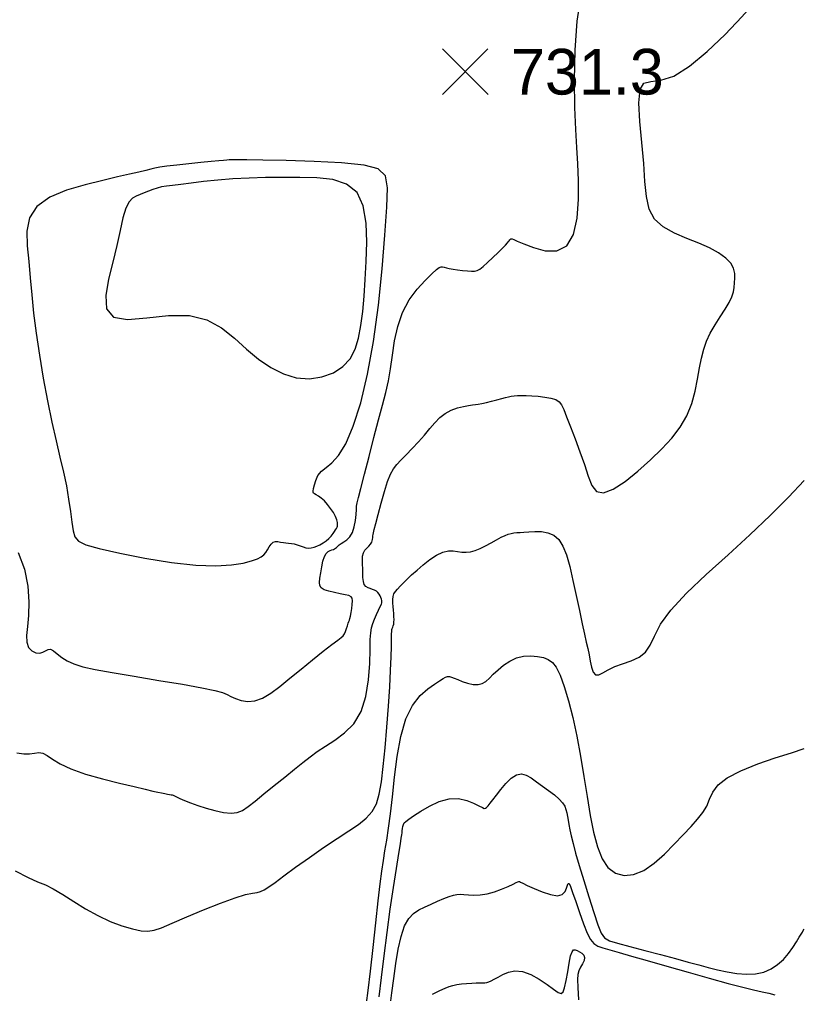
# Model space of a CAD drawing. Extents: x 2566142 to 2571431, y 418755 to 421584.
# Drawn here: x 2567510.9 to 2567768.3, y 419780.6 to 420100.3 of the extents above; entities that cross this region are included whole.
import ezdxf

# ---------------------------------------------------------------- set-up
doc = ezdxf.new("R2010")
doc.units = 0
for name, color, linetype in [('Contour_ADS_Major', 7, 'Continuous'), ('Contour_ADS_Minor', 7, 'Continuous'), ('Contour_ADS_Spot_Elevation', 7, 'Continuous')]:
    doc.layers.add(name, color=color, linetype=linetype)

# ---------------------------------------------------------------- blocks, each defined once
blk = doc.blocks.new('S750')
at = {"layer": 'Contour_ADS_Spot_Elevation'}
for p, q in [((-0.5, 0.498), (0.5, -0.498)), ((-0.498, -0.5), (0.498, 0.5))]:
    blk.add_line(p, q, dxfattribs=at)

msp = doc.modelspace()

# ---------------------------------------------------------------- linework, layer by layer
at = {"layer": 'Contour_ADS_Major'}
for points in [[(2567617.86, 419911.52), (2567616.2, 419911.84), (2567614.29, 419912.21), (2567612.43, 419912.64), (2567610.9, 419913.15), (2567609.95, 419913.75), (2567609.5, 419914.52), (2567609.41, 419915.55), (2567609.54, 419916.93), (2567609.78, 419918.69), (2567610.1, 419920.63), (2567610.5, 419922.5), (2567611, 419924.04), (2567611.58, 419925.07), (2567612.22, 419925.67), (2567612.85, 419925.99), (2567613.43, 419926.18), (2567613.93, 419926.36), (2567614.34, 419926.56), (2567614.67, 419926.77), (2567614.95, 419927), (2567615.2, 419927.25), (2567615.48, 419927.54), (2567615.88, 419927.88), (2567616.49, 419928.3), (2567617.35, 419928.82), (2567618.36, 419929.54), (2567619.37, 419930.55), (2567620.22, 419931.96), (2567620.82, 419933.8), (2567621.19, 419935.85), (2567621.39, 419937.82), (2567621.49, 419939.43), (2567621.57, 419940.54), (2567621.74, 419941.63), (2567622.14, 419943.36), (2567622.91, 419946.35), (2567624.12, 419951.03), (2567625.64, 419956.85), (2567627.27, 419963.05), (2567628.81, 419968.87), (2567630.12, 419973.73), (2567631.19, 419977.87), (2567632.06, 419981.71), (2567632.75, 419985.68), (2567633.35, 419990.09), (2567634.05, 419994.81), (2567635.06, 419999.57), (2567636.63, 420004.12), (2567638.88, 420008.22), (2567641.5, 420011.77), (2567644.11, 420014.66), (2567646.31, 420016.81), (2567647.8, 420018.17), (2567648.71, 420018.89), (2567649.28, 420019.15), (2567649.75, 420019.14), (2567650.31, 420019.01), (2567651.05, 420018.82), (2567652.01, 420018.59), (2567653.24, 420018.35), (2567654.74, 420018.13), (2567656.38, 420017.93), (2567657.96, 420017.79), (2567659.31, 420017.7), (2567660.32, 420017.7), (2567661.14, 420017.89), (2567661.99, 420018.36), (2567663.09, 420019.24), (2567664.59, 420020.56), (2567666.31, 420022.15), (2567668.03, 420023.77), (2567669.48, 420025.19), (2567670.49, 420026.22), (2567671.11, 420026.92), (2567671.47, 420027.37), (2567671.69, 420027.68), (2567671.87, 420027.92), (2567672.04, 420028.12), (2567672.21, 420028.25), (2567672.38, 420028.31), (2567672.61, 420028.27), (2567673.16, 420028.05), (2567674.34, 420027.54), (2567676.45, 420026.65), (2567679.65, 420025.4), (2567683.48, 420024.38), (2567687.32, 420024.32), (2567690.57, 420025.95), (2567692.74, 420029.73), (2567693.94, 420035.11), (2567694.43, 420041.27), (2567694.45, 420047.38), (2567694.23, 420052.88), (2567693.89, 420058.23), (2567693.52, 420064.17), (2567693.24, 420071.42), (2567693.13, 420080.37), (2567693.34, 420090.18), (2567693.99, 420099.68), (2567695.24, 420107.69)], [(2567510.41, 419925.41), (2567512.52, 419919.92), (2567513.63, 419914.33), (2567513.99, 419909.12), (2567513.84, 419904.69), (2567513.47, 419901.07), (2567513.17, 419898.17), (2567513.24, 419895.91), (2567513.89, 419894.21), (2567514.97, 419893.06), (2567516.26, 419892.43), (2567517.51, 419892.31), (2567518.55, 419892.62), (2567519.42, 419893.13), (2567520.24, 419893.55), (2567521.09, 419893.6), (2567522.09, 419893.08), (2567523.28, 419892.12), (2567524.73, 419890.94), (2567526.5, 419889.77), (2567528.7, 419888.78), (2567531.65, 419887.89), (2567535.73, 419886.99), (2567541.32, 419885.97), (2567548.56, 419884.74), (2567556.6, 419883.41), (2567564.36, 419882.1), (2567570.76, 419880.96), (2567575.02, 419880.09), (2567577.55, 419879.4), (2567579.06, 419878.8), (2567580.29, 419878.15), (2567581.81, 419877.42), (2567583.68, 419876.76), (2567585.82, 419876.43), (2567588.16, 419876.65), (2567590.66, 419877.6), (2567593.35, 419879.23), (2567596.32, 419881.43), (2567599.66, 419884.11), (2567603.36, 419887.11), (2567607.13, 419890.16), (2567610.61, 419892.95), (2567613.45, 419895.18), (2567615.37, 419896.62), (2567616.53, 419897.48), (2567617.18, 419898.05), (2567617.59, 419898.63), (2567617.94, 419899.43), (2567618.28, 419900.38), (2567618.59, 419901.34), (2567618.85, 419902.16), (2567619.04, 419902.73), (2567619.21, 419903.2), (2567619.36, 419903.73), (2567619.53, 419904.5), (2567619.75, 419905.63), (2567619.96, 419906.97), (2567620.12, 419908.33), (2567620.18, 419909.5), (2567620.08, 419910.32), (2567619.73, 419910.86), (2567619.02, 419911.22), (2567617.86, 419911.52)], [(2567632.57, 419776.44), (2567633.15, 419780.86), (2567633.76, 419785.61), (2567634.45, 419790.47), (2567635.26, 419795.18), (2567636.21, 419799.4), (2567637.34, 419802.84), (2567638.67, 419805.29), (2567640.21, 419806.93), (2567641.95, 419808.08), (2567643.89, 419809.01), (2567646.01, 419809.96), (2567648.17, 419810.92), (2567650.21, 419811.78), (2567651.96, 419812.47), (2567653.33, 419812.92), (2567654.46, 419813.15), (2567655.53, 419813.22), (2567656.76, 419813.16), (2567658.28, 419813.04), (2567660.1, 419812.95), (2567662.17, 419813.01), (2567664.44, 419813.34), (2567666.84, 419814), (2567669.19, 419814.86), (2567671.29, 419815.76), (2567672.94, 419816.52), (2567674, 419817.02), (2567674.56, 419817.28), (2567674.81, 419817.38), (2567674.9, 419817.39), (2567675, 419817.35), (2567675.34, 419817.19), (2567676.12, 419816.81), (2567677.58, 419816.12), (2567679.82, 419815.09), (2567682.52, 419813.97), (2567685.24, 419813.08), (2567687.54, 419812.73), (2567689.1, 419813.15), (2567690.01, 419814.09), (2567690.49, 419815.23), (2567690.76, 419816.24), (2567690.99, 419816.79), (2567691.31, 419816.69), (2567691.79, 419815.76), (2567692.51, 419813.82), (2567693.52, 419810.82), (2567694.73, 419807.2), (2567696.02, 419803.55), (2567697.25, 419800.45), (2567698.35, 419798.32), (2567699.46, 419797), (2567700.77, 419796.2), (2567702.47, 419795.6), (2567704.74, 419794.93), (2567707.79, 419794.07), (2567711.8, 419792.95), (2567716.98, 419791.49), (2567723.38, 419789.66), (2567730.42, 419787.64), (2567737.37, 419785.66), (2567743.53, 419783.96), (2567748.33, 419782.71), (2567751.94, 419781.84), (2567754.69, 419781.23), (2567756.9, 419780.73), (2567758.86, 419780.26)]]:
    msp.add_lwpolyline(points, dxfattribs=at)
at = {"layer": 'Contour_ADS_Minor'}
for points in [[(2567722.24, 420032.19), (2567719.37, 420034.77), (2567717.62, 420038.05), (2567716.71, 420042.13), (2567716.25, 420047.1), (2567715.85, 420053.04), (2567715.23, 420059.87), (2567714.6, 420066.81), (2567714.29, 420072.94), (2567714.63, 420077.31), (2567715.9, 420079.36), (2567718.16, 420079.96), (2567721.42, 420080.32), (2567725.69, 420081.67), (2567730.9, 420084.93), (2567736.67, 420089.72), (2567742.53, 420095.34), (2567748.02, 420101.11), (2567752.79, 420106.42), (2567756.87, 420111.1), (2567760.4, 420115.06), (2567763.53, 420118.22), (2567766.33, 420120.54), (2567768.66, 420122.25)], [(2567624, 420052.45), (2567616.6, 420053.22), (2567607.59, 420053.7), (2567598.47, 420053.98), (2567590.73, 420054.13), (2567585.47, 420054.2), (2567582.36, 420054.23), (2567580.7, 420054.22), (2567579.77, 420054.19), (2567578.96, 420054.12), (2567577.89, 420054.01), (2567576.28, 420053.85), (2567573.84, 420053.61), (2567570.43, 420053.28), (2567566.48, 420052.9), (2567562.56, 420052.5), (2567559.24, 420052.12), (2567556.94, 420051.8), (2567555.34, 420051.49), (2567553.97, 420051.15), (2567552.36, 420050.73), (2567550.1, 420050.19), (2567547.03, 420049.49), (2567543.09, 420048.59), (2567538.2, 420047.46), (2567532.41, 420046.06), (2567526.36, 420044.25), (2567520.82, 420041.92), (2567516.58, 420038.93), (2567514.17, 420035.19), (2567513.29, 420030.83), (2567513.38, 420025.99), (2567513.91, 420020.86), (2567513.91, 420020.86)], [(2567513.91, 420020.86), (2567514.43, 420015.53), (2567514.93, 420009.93), (2567515.53, 420003.89), (2567516.33, 419997.29), (2567517.4, 419990.06), (2567518.67, 419982.52), (2567520.07, 419975.08), (2567521.5, 419968.15), (2567522.87, 419962.02), (2567524.15, 419956.61), (2567525.29, 419951.73), (2567526.26, 419947.19), (2567527.02, 419942.84), (2567527.62, 419938.83), (2567528.11, 419935.33), (2567528.53, 419932.52), (2567529.05, 419930.52), (2567530.2, 419929.08), (2567532.66, 419927.89), (2567537.07, 419926.65), (2567543.79, 419925.12), (2567552.04, 419923.51), (2567560.74, 419922.09), (2567568.82, 419921.17), (2567575.4, 419920.94), (2567580.5, 419921.27), (2567584.32, 419921.91), (2567587.08, 419922.65), (2567588.99, 419923.31), (2567590.26, 419923.91), (2567591.1, 419924.56), (2567591.71, 419925.32), (2567592.27, 419926.25), (2567592.85, 419927.24), (2567593.46, 419928.12), (2567594.14, 419928.74), (2567594.91, 419929), (2567595.75, 419928.97), (2567596.63, 419928.79), (2567597.51, 419928.6), (2567598.38, 419928.49), (2567599.25, 419928.43), (2567600.14, 419928.36), (2567601.05, 419928.2), (2567602.01, 419927.91), (2567602.99, 419927.55), (2567603.97, 419927.2), (2567604.92, 419926.93), (2567605.82, 419926.82), (2567606.7, 419926.87), (2567607.59, 419927.08), (2567608.53, 419927.43), (2567609.54, 419927.91), (2567610.58, 419928.5), (2567611.58, 419929.19), (2567612.48, 419929.95), (2567613.24, 419930.76), (2567613.85, 419931.55), (2567614.33, 419932.26), (2567614.68, 419932.83), (2567614.92, 419933.2), (2567615.08, 419933.46), (2567615.18, 419933.71), (2567615.24, 419934.03), (2567615.28, 419934.53), (2567615.24, 419935.22), (2567615.05, 419936.1), (2567614.63, 419937.18), (2567613.94, 419938.45), (2567613.05, 419939.79), (2567612.03, 419941.1), (2567610.98, 419942.26), (2567609.98, 419943.16), (2567609.08, 419943.83), (2567608.33, 419944.3), (2567607.76, 419944.62), (2567607.41, 419944.84), (2567607.26, 419945.09), (2567607.27, 419945.53), (2567607.42, 419946.31), (2567607.69, 419947.53), (2567608.15, 419949.03), (2567608.89, 419950.6), (2567610, 419952.04), (2567611.54, 419953.27), (2567613.46, 419954.77), (2567615.65, 419957.14), (2567618.02, 419961), (2567620.48, 419966.81), (2567622.91, 419974.5), (2567625.17, 419983.85), (2567627.14, 419994.62), (2567628.72, 420006.47), (2567629.93, 420018.46), (2567630.82, 420029.54), (2567631.44, 420038.64), (2567631.7, 420044.98), (2567631.03, 420048.95), (2567628.7, 420051.21), (2567624, 420052.45)], [(2567623.53, 419924.17), (2567623.78, 419925.24), (2567624.28, 419926.08), (2567624.92, 419926.77), (2567625.6, 419927.39), (2567626.18, 419928.05), (2567626.57, 419928.79), (2567626.79, 419929.58), (2567626.9, 419930.3), (2567626.94, 419930.88), (2567626.97, 419931.3), (2567627.08, 419931.85), (2567627.34, 419932.91), (2567627.83, 419934.85), (2567628.62, 419937.87), (2567629.61, 419941.56), (2567630.7, 419945.34), (2567631.75, 419948.65), (2567632.7, 419951.06), (2567633.64, 419952.78), (2567634.73, 419954.18), (2567636.09, 419955.63), (2567637.84, 419957.41), (2567639.83, 419959.47), (2567641.91, 419961.68), (2567643.89, 419963.89), (2567645.65, 419966), (2567647.28, 419967.92), (2567648.91, 419969.61), (2567650.67, 419970.99), (2567652.65, 419972.04), (2567654.71, 419972.78), (2567656.67, 419973.28), (2567658.32, 419973.59), (2567659.57, 419973.76), (2567660.56, 419973.87), (2567661.52, 419973.99), (2567662.68, 419974.2), (2567664.19, 419974.55), (2567665.91, 419975), (2567667.66, 419975.48), (2567669.21, 419975.91), (2567670.44, 419976.24), (2567671.43, 419976.48), (2567672.32, 419976.65), (2567673.26, 419976.77), (2567674.38, 419976.86), (2567675.71, 419976.9), (2567677.29, 419976.89), (2567679.13, 419976.8), (2567681.22, 419976.64), (2567683.38, 419976.37), (2567685.38, 419976), (2567687, 419975.51), (2567688.1, 419974.85), (2567688.86, 419973.84), (2567689.56, 419972.26), (2567690.46, 419969.89), (2567691.75, 419966.61), (2567693.3, 419962.67), (2567694.91, 419958.42), (2567696.38, 419954.22), (2567697.59, 419950.41), (2567698.81, 419947.35), (2567700.38, 419945.41), (2567702.65, 419944.94), (2567705.85, 419946.15), (2567709.73, 419948.69), (2567713.93, 419952.06), (2567718.07, 419955.74), (2567721.83, 419959.34), (2567725.11, 419962.88), (2567727.86, 419966.46), (2567730.04, 419970.22), (2567731.63, 419974.2), (2567732.74, 419978.27), (2567733.55, 419982.24), (2567734.2, 419985.91), (2567734.84, 419989.15), (2567735.57, 419992.05), (2567736.5, 419994.74), (2567737.71, 419997.37), (2567739.25, 420000.04), (2567740.94, 420002.68), (2567742.56, 420005.16), (2567743.89, 420007.38), (2567744.77, 420009.26), (2567745.27, 420010.87), (2567745.52, 420012.34), (2567745.68, 420013.8), (2567745.8, 420015.33), (2567745.77, 420016.95), (2567745.37, 420018.61), (2567744.42, 420020.3), (2567742.77, 420021.98), (2567740.43, 420023.64), (2567737.47, 420025.28), (2567733.94, 420026.87), (2567729.96, 420028.44), (2567725.92, 420030.15), (2567722.24, 420032.19)], [(2567684.41, 419931.86), (2567686.37, 419931.06), (2567687.98, 419929.63), (2567689.3, 419927.48), (2567690.45, 419924.56), (2567691.53, 419920.8), (2567692.62, 419916.21), (2567693.71, 419911.21), (2567694.73, 419906.29), (2567695.63, 419901.97), (2567696.38, 419898.59), (2567696.98, 419895.98), (2567697.48, 419893.83), (2567697.91, 419891.81), (2567698.3, 419889.71), (2567698.73, 419887.71), (2567699.29, 419886.12), (2567700.04, 419885.21), (2567701.06, 419885.18), (2567702.41, 419885.82), (2567704.15, 419886.84), (2567706.32, 419887.92), (2567708.92, 419888.86), (2567711.69, 419889.8), (2567714.31, 419890.97), (2567716.44, 419892.61), (2567717.95, 419894.9), (2567719.35, 419897.95), (2567721.37, 419901.79), (2567724.71, 419906.48), (2567729.84, 419912.01), (2567736.33, 419918.15), (2567743.52, 419924.64), (2567750.73, 419931.18), (2567757.39, 419937.53), (2567763.34, 419943.5), (2567768.51, 419948.94)], [(2567509.48, 419820.87), (2567513.72, 419818.72), (2567516.82, 419817.34), (2567519.37, 419816.26), (2567521.97, 419814.97), (2567525.08, 419813.11), (2567528.67, 419810.85), (2567532.57, 419808.45), (2567536.63, 419806.19), (2567540.67, 419804.31), (2567544.51, 419802.86), (2567547.96, 419801.83), (2567550.83, 419801.23), (2567553.06, 419801.06), (2567555.11, 419801.38), (2567557.56, 419802.24), (2567561, 419803.7), (2567565.78, 419805.75), (2567571.34, 419808.08), (2567576.9, 419810.32), (2567581.69, 419812.09), (2567585.11, 419813.12), (2567587.36, 419813.6), (2567588.87, 419813.82), (2567590.02, 419814.08), (2567591.21, 419814.63), (2567592.71, 419815.6), (2567594.78, 419817.11), (2567597.68, 419819.25), (2567601.55, 419822.05), (2567606.05, 419825.25), (2567610.74, 419828.52), (2567615.18, 419831.52), (2567619.01, 419834.01), (2567622.18, 419836.15), (2567624.72, 419838.19), (2567626.66, 419840.37), (2567628.05, 419842.93), (2567629.02, 419846.1), (2567629.74, 419850.09), (2567630.33, 419855.11), (2567630.92, 419861.24), (2567631.51, 419868.03), (2567632.03, 419874.9), (2567632.45, 419881.28), (2567632.73, 419886.69), (2567632.9, 419891.07), (2567632.99, 419894.47), (2567633.03, 419896.94), (2567633.06, 419898.56), (2567633.1, 419899.53), (2567633.17, 419900.09), (2567633.27, 419900.47), (2567633.41, 419900.86), (2567633.58, 419901.32), (2567633.74, 419901.88), (2567633.84, 419902.55), (2567633.87, 419903.37), (2567633.84, 419904.3), (2567633.76, 419905.34), (2567633.65, 419906.45), (2567633.52, 419907.62), (2567633.43, 419908.78), (2567633.43, 419909.9), (2567633.55, 419910.91), (2567633.84, 419911.78), (2567634.32, 419912.57), (2567634.98, 419913.37), (2567635.83, 419914.27), (2567636.88, 419915.33), (2567638.14, 419916.57), (2567639.64, 419917.99), (2567641.42, 419919.59), (2567643.46, 419921.33), (2567645.66, 419923.04), (2567647.85, 419924.5), (2567649.9, 419925.52), (2567651.69, 419925.95), (2567653.27, 419925.95), (2567654.71, 419925.72), (2567656.09, 419925.48), (2567657.49, 419925.42), (2567658.95, 419925.59), (2567660.49, 419925.99), (2567662.14, 419926.63), (2567663.92, 419927.5), (2567665.73, 419928.5), (2567667.46, 419929.49), (2567669.01, 419930.35), (2567670.3, 419930.97), (2567671.37, 419931.38), (2567672.31, 419931.63), (2567673.22, 419931.79), (2567674.16, 419931.89), (2567675.23, 419931.97), (2567676.53, 419932.04), (2567678.14, 419932.13), (2567680.09, 419932.23), (2567682.25, 419932.2), (2567684.41, 419931.86)], [(2567509.96, 419859.63), (2567512.25, 419859.3), (2567514.17, 419859.34), (2567515.8, 419859.56), (2567517.24, 419859.68), (2567518.58, 419859.47), (2567519.96, 419858.71), (2567521.71, 419857.5), (2567524.18, 419855.99), (2567527.74, 419854.33), (2567532.56, 419852.66), (2567538.12, 419851.08), (2567543.69, 419849.67), (2567548.54, 419848.52), (2567552.14, 419847.67), (2567554.63, 419847.09), (2567556.33, 419846.71), (2567557.55, 419846.44), (2567558.58, 419846.24), (2567559.44, 419846.08), (2567560.14, 419845.96), (2567560.65, 419845.86), (2567561, 419845.79), (2567561.31, 419845.68), (2567561.75, 419845.49), (2567562.45, 419845.15), (2567563.56, 419844.64), (2567565.1, 419843.97), (2567567.05, 419843.19), (2567569.42, 419842.33), (2567572.16, 419841.44), (2567575.06, 419840.65), (2567577.87, 419840.07), (2567580.35, 419839.82), (2567582.35, 419840.02), (2567584.1, 419840.72), (2567585.95, 419841.96), (2567588.23, 419843.77), (2567591.16, 419846.15), (2567594.52, 419848.87), (2567597.97, 419851.65), (2567601.17, 419854.24), (2567603.88, 419856.42), (2567606.29, 419858.3), (2567608.67, 419860.04), (2567611.31, 419861.79), (2567614.38, 419863.74), (2567617.61, 419866.13), (2567620.64, 419869.18), (2567623.07, 419873.15), (2567624.64, 419878.12), (2567625.49, 419883.61), (2567625.86, 419888.95), (2567625.98, 419893.5), (2567626.07, 419896.77), (2567626.2, 419899.01), (2567626.45, 419900.63), (2567626.85, 419902.02), (2567627.43, 419903.52), (2567628.12, 419905.05), (2567628.8, 419906.46), (2567629.35, 419907.61), (2567629.7, 419908.39), (2567629.86, 419908.88), (2567629.88, 419909.23), (2567629.81, 419909.59), (2567629.69, 419910.05), (2567629.51, 419910.6), (2567629.27, 419911.18), (2567628.96, 419911.73), (2567628.56, 419912.22), (2567628.07, 419912.63), (2567627.49, 419912.98), (2567626.82, 419913.26), (2567626.07, 419913.5), (2567625.31, 419913.78), (2567624.62, 419914.21), (2567624.09, 419914.89), (2567623.79, 419915.88), (2567623.65, 419917.14), (2567623.61, 419918.55), (2567623.58, 419920.04), (2567623.51, 419921.52), (2567623.47, 419922.91), (2567623.53, 419924.17)], [(2567658.02, 419882.5), (2567659.8, 419882.09), (2567661.44, 419881.99), (2567662.8, 419882.32), (2567663.98, 419883.05), (2567665.15, 419884.1), (2567666.45, 419885.42), (2567668.02, 419886.9), (2567669.85, 419888.4), (2567671.89, 419889.74), (2567674.09, 419890.74), (2567676.41, 419891.29), (2567678.74, 419891.42), (2567680.94, 419891.24), (2567682.89, 419890.85), (2567684.51, 419890.27), (2567685.89, 419889.31), (2567687.14, 419887.68), (2567688.4, 419885.11), (2567689.76, 419881.42), (2567691.18, 419876.73), (2567692.59, 419871.21), (2567693.91, 419865.08), (2567695.1, 419858.55), (2567696.2, 419851.86), (2567697.23, 419845.28), (2567698.27, 419839.1), (2567699.36, 419833.55), (2567700.61, 419828.77), (2567702.15, 419824.87), (2567704.1, 419821.95), (2567706.53, 419820.11), (2567709.37, 419819.36), (2567712.51, 419819.67), (2567715.85, 419821.03), (2567719.27, 419823.37), (2567722.66, 419826.35), (2567725.88, 419829.6), (2567728.82, 419832.74), (2567731.37, 419835.45), (2567733.51, 419837.82), (2567735.23, 419840), (2567736.53, 419842.15), (2567737.48, 419844.39), (2567738.55, 419846.71), (2567740.29, 419849.08), (2567743.24, 419851.45), (2567747.75, 419853.76), (2567753.27, 419855.96), (2567759.04, 419857.95), (2567764.33, 419859.66), (2567768.53, 419861.08)], [(2567624.82, 419777.42), (2567625.4, 419781.6), (2567626.15, 419787.99), (2567626.99, 419795.77), (2567627.85, 419803.83), (2567628.64, 419811.06), (2567629.3, 419816.63), (2567629.85, 419820.84), (2567630.36, 419824.25), (2567630.88, 419827.45), (2567631.44, 419830.93), (2567632.05, 419834.93), (2567632.7, 419839.62), (2567633.35, 419845.16), (2567634.03, 419851.6), (2567634.88, 419858.43), (2567636.04, 419865.03), (2567637.68, 419870.78), (2567639.88, 419875.19), (2567642.4, 419878.39), (2567644.93, 419880.64), (2567647.15, 419882.2), (2567648.8, 419883.3), (2567649.98, 419884.04), (2567650.81, 419884.48), (2567651.46, 419884.67), (2567652.06, 419884.67), (2567652.74, 419884.5), (2567653.6, 419884.16), (2567654.76, 419883.68), (2567656.28, 419883.08), (2567658.02, 419882.5)], [(2567670.62, 419849.58), (2567672.37, 419851.29), (2567674.09, 419852.43), (2567675.69, 419852.75), (2567677.24, 419852.34), (2567678.84, 419851.41), (2567680.61, 419850.15), (2567682.58, 419848.73), (2567684.63, 419847.25), (2567686.53, 419845.79), (2567688.11, 419844.42), (2567689.2, 419843.19), (2567689.89, 419842.08), (2567690.29, 419841.01), (2567690.55, 419839.93), (2567690.76, 419838.78), (2567690.98, 419837.5), (2567691.23, 419836.05), (2567691.57, 419834.36), (2567692.01, 419832.36), (2567692.63, 419829.89), (2567693.49, 419826.73), (2567694.65, 419822.69), (2567696.15, 419817.73), (2567697.81, 419812.36), (2567699.43, 419807.28), (2567700.81, 419803.15), (2567701.87, 419800.47), (2567702.96, 419798.91), (2567704.6, 419797.98), (2567707.26, 419797.18), (2567711.26, 419796.1), (2567716.17, 419794.8), (2567721.38, 419793.41), (2567726.28, 419792.09), (2567730.41, 419790.96), (2567733.89, 419790.01), (2567737.01, 419789.18), (2567740.05, 419788.44), (2567743.21, 419787.76), (2567746.43, 419787.23), (2567749.6, 419786.97), (2567752.58, 419787.09), (2567755.27, 419787.69), (2567757.67, 419788.73), (2567759.81, 419790.13), (2567761.71, 419791.85), (2567763.38, 419793.78), (2567764.82, 419795.76), (2567766, 419797.6), (2567766.9, 419799.1), (2567767.52, 419800.14), (2567767.94, 419800.81), (2567768.23, 419801.29), (2567768.51, 419801.73)], [(2567629.02, 419779.55), (2567629.78, 419785.85), (2567630.64, 419793.04), (2567631.59, 419800.67), (2567632.63, 419808.29), (2567633.68, 419815.44), (2567634.65, 419821.67), (2567635.42, 419826.54), (2567635.94, 419829.76), (2567636.24, 419831.65), (2567636.39, 419832.69), (2567636.48, 419833.37), (2567636.55, 419834.05), (2567636.64, 419834.79), (2567636.76, 419835.49), (2567636.94, 419836.11), (2567637.21, 419836.61), (2567637.74, 419837.12), (2567638.71, 419837.83), (2567640.3, 419838.91), (2567642.63, 419840.45), (2567645.51, 419842.15), (2567648.7, 419843.64), (2567651.94, 419844.54), (2567654.98, 419844.58), (2567657.71, 419843.99), (2567659.99, 419843.09), (2567661.73, 419842.21), (2567662.85, 419841.63), (2567663.5, 419841.38), (2567663.9, 419841.43), (2567664.25, 419841.73), (2567664.72, 419842.27), (2567665.39, 419843.09), (2567666.29, 419844.23), (2567667.47, 419845.74), (2567668.95, 419847.61), (2567670.62, 419849.58)], [(2567646.48, 419780.47), (2567648.86, 419781.58), (2567650.65, 419782.39), (2567652, 419782.95), (2567653.17, 419783.32), (2567654.43, 419783.59), (2567655.97, 419783.8), (2567657.67, 419783.96), (2567659.36, 419784.08), (2567660.85, 419784.14), (2567662.01, 419784.16), (2567662.9, 419784.16), (2567663.63, 419784.19), (2567664.29, 419784.29), (2567664.99, 419784.48), (2567665.8, 419784.82), (2567666.79, 419785.31), (2567668.02, 419786), (2567669.55, 419786.85), (2567671.39, 419787.63), (2567673.55, 419788.06), (2567676.01, 419787.86), (2567678.74, 419786.86), (2567681.52, 419785.3), (2567684.11, 419783.57), (2567686.24, 419782.04), (2567687.75, 419781.02), (2567688.74, 419780.68), (2567689.38, 419781.16), (2567689.88, 419782.56), (2567690.37, 419784.9), (2567690.87, 419787.77), (2567691.37, 419790.64), (2567691.85, 419792.97), (2567692.3, 419794.37), (2567692.77, 419794.96), (2567693.31, 419795), (2567693.97, 419794.71), (2567694.77, 419794.32), (2567695.57, 419793.84), (2567696.19, 419793.22), (2567696.45, 419792.45), (2567696.25, 419791.49), (2567695.73, 419790.41), (2567695.09, 419789.26), (2567694.53, 419788.1), (2567694.22, 419786.9), (2567694.14, 419785.24), (2567694.23, 419782.62), (2567694.42, 419778.52)]]:
    msp.add_lwpolyline(points, dxfattribs=at)
msp.add_lwpolyline([(2567566.65, 420003.16), (2567572.42, 420001.71), (2567577.26, 419999.05), (2567581.49, 419995.68), (2567585.44, 419992.13), (2567589.4, 419988.85), (2567593.44, 419986.07), (2567597.56, 419983.96), (2567601.77, 419982.69), (2567606.05, 419982.38), (2567610.19, 419982.97), (2567613.95, 419984.33), (2567617.09, 419986.36), (2567619.42, 419988.95), (2567621.06, 419992.08), (2567622.18, 419995.71), (2567622.97, 419999.82), (2567623.58, 420004.4), (2567624.05, 420009.44), (2567624.42, 420014.94), (2567624.73, 420020.9), (2567624.93, 420027.23), (2567624.73, 420033.47), (2567623.77, 420039.06), (2567621.7, 420043.45), (2567618.28, 420046.25), (2567613.76, 420047.73), (2567608.51, 420048.31), (2567602.9, 420048.43), (2567597.26, 420048.43), (2567591.68, 420048.36), (2567586.24, 420048.21), (2567580.97, 420047.94), (2567575.95, 420047.54), (2567571.31, 420047.07), (2567567.21, 420046.59), (2567563.8, 420046.16), (2567561.15, 420045.84), (2567559.13, 420045.57), (2567557.51, 420045.3), (2567556.08, 420044.94), (2567554.67, 420044.47), (2567553.25, 420043.91), (2567551.86, 420043.34), (2567550.51, 420042.81), (2567549.23, 420042.33), (2567548.02, 420041.64), (2567546.88, 420040.41), (2567545.84, 420038.32), (2567544.86, 420035.14), (2567543.89, 420030.99), (2567542.82, 420026.09), (2567541.55, 420020.67), (2567540.14, 420015.01), (2567539.2, 420009.69), (2567539.46, 420005.34), (2567541.7, 420002.61), (2567546.35, 420001.86), (2567552.73, 420002.36), (2567559.83, 420003.13), (2567566.65, 420003.16)], close=True, dxfattribs=at)

# ---------------------------------------------------------------- block references
at = {"layer": 'Contour_ADS_Spot_Elevation', "xscale": 15, "yscale": 15}
msp.add_blockref('S750', (2567657.24, 420083.13), dxfattribs=at)

# ---------------------------------------------------------------- texts
at = {"layer": 'Contour_ADS_Spot_Elevation'}
msp.add_text('731.3', height=15, dxfattribs=at).set_placement((2567672.24, 420075.63))

doc.saveas('drawing.dxf')
